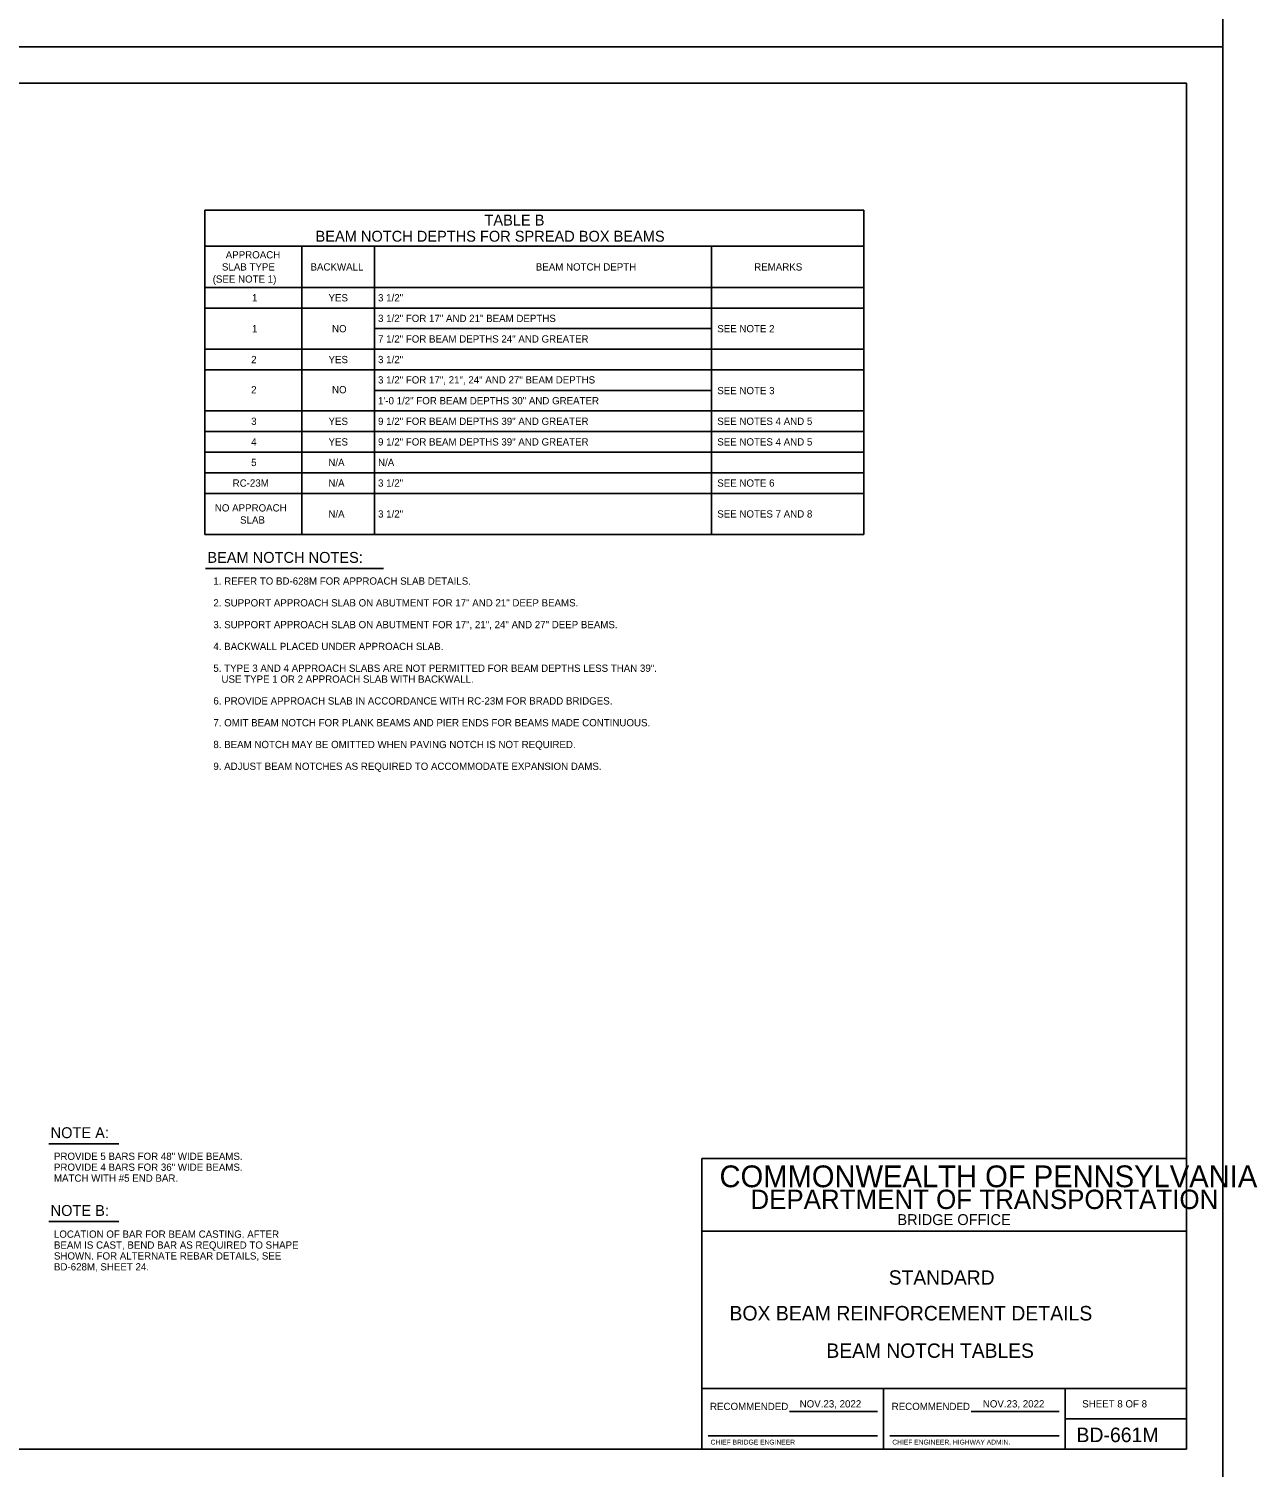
# Model space of a CAD drawing. Extents: x 639331 to 643089, y 299088 to 300975.
# Drawn here: x 642582 to 643089, y 299689 to 300283 of the extents above; entities that cross this region are included whole.
import ezdxf

# ---------------------------------------------------------------- set-up
doc = ezdxf.new("R2010")
doc.units = 0
for name, color, linetype in [('1', 7, 'Continuous'), ('DATES', 7, 'Continuous'), ('PLT-BNDY', 7, 'Continuous'), ('SIGNATORY TITLES', 7, 'Continuous')]:
    doc.layers.add(name, color=color, linetype=linetype)

msp = doc.modelspace()

# ---------------------------------------------------------------- linework, layer by layer
at = {"layer": '1'}
for p, q in [((643075.06, 300275.66), (643075.06, 300275.66)), ((642274.06, 300260.66), (643060.06, 300260.66)), ((643060.06, 300260.66), (643060.06, 299696.66)), ((642654.82, 300208.32), (642654.82, 300074.32)), ((642926.91, 300208.32), (642654.82, 300208.32)), ((642926.91, 300208.32), (642926.91, 300074.32)), ((642926.91, 300193.32), (642654.82, 300193.32)), ((642694.82, 300193.32), (642694.82, 300074.32)), ((642724.82, 300193.32), (642724.82, 300074.32)), ((642864.05, 300193.32), (642864.05, 300074.32)), ((642926.91, 300176.32), (642654.82, 300176.32)), ((642926.91, 300167.82), (642654.82, 300167.82)), ((642864.05, 300159.32), (642724.82, 300159.32)), ((642926.91, 300150.82), (642654.82, 300150.82)), ((642926.91, 300142.32), (642654.82, 300142.32)), ((642864.05, 300133.82), (642724.82, 300133.82)), ((642926.91, 300125.32), (642654.82, 300125.32)), ((642926.91, 300116.82), (642654.82, 300116.82)), ((642926.91, 300108.32), (642654.82, 300108.32)), ((642926.91, 300099.82), (642654.82, 300099.82)), ((642926.91, 300091.32), (642654.82, 300091.32)), ((642926.91, 300074.32), (642654.82, 300074.32)), ((642655.15, 300060.3), (642728.57, 300060.3)), ((642590.44, 299822.74), (642619.28, 299822.74)), ((643060.06, 299816.66), (642860.06, 299816.66)), ((642860.06, 299816.66), (642860.06, 299696.66)), ((643060.06, 299696.66), (643060.06, 299816.66)), ((642590.44, 299790.6), (642619.28, 299790.6)), ((643060.06, 299786.66), (642860.06, 299786.66)), ((643060.06, 299721.66), (642860.06, 299721.66)), ((642935.06, 299696.66), (642935.06, 299721.66)), ((643010.06, 299721.66), (643010.06, 299696.66)), ((642896.15, 299712.16), (642932.56, 299712.16)), ((642971.15, 299712.16), (643007.56, 299712.16)), ((643010.06, 299709.16), (643060.06, 299709.16)), ((642862.56, 299702.16), (642932.56, 299702.16)), ((642937.56, 299702.16), (643007.56, 299702.16)), ((643060.06, 299696.66), (642274.06, 299696.66)), ((642860.06, 299696.66), (643060.06, 299696.66))]:
    msp.add_line(p, q, dxfattribs=at)
at = {"layer": 'PLT-BNDY'}
for points in [[(642234.06, 300869.66), (643075.06, 300869.66), (643075.06, 300275.66), (642234.06, 300275.66)], [(642234.06, 300275.66), (643075.06, 300275.66), (643075.06, 299681.66), (642234.06, 299681.66)]]:
    msp.add_lwpolyline(points, close=True, dxfattribs=at)

# ---------------------------------------------------------------- texts
at = {"layer": '1'}
for s, height, p in [('TABLE B', 4.5, (642770.29, 300201.9)), ('BEAM NOTCH DEPTHS FOR SPREAD BOX BEAMS', 4.5, (642700.55, 300195.24)), ('3 1/2"', 3, (642726.35, 300170.57)), ('3 1/2" FOR 17" AND 21" BEAM DEPTHS', 3, (642726.35, 300162.07)), ('SEE NOTE 2', 3, (642866.39, 300157.82)), ('7 1/2" FOR BEAM DEPTHS 24" AND GREATER', 3, (642726.35, 300153.57)), ('3 1/2"', 3, (642726.35, 300145.07)), ('3 1/2" FOR 17", 21", 24" AND 27" BEAM DEPTHS', 3, (642726.35, 300136.68)), ('1\'-0 1/2" FOR BEAM DEPTHS 30" AND GREATER', 3, (642726.35, 300128.07)), ('SEE NOTE 3', 3, (642866.39, 300132.26)), ('9 1/2" FOR BEAM DEPTHS 39" AND GREATER', 3, (642726.35, 300119.57)), ('SEE NOTES 4 AND 5', 3, (642866.39, 300119.57)), ('9 1/2" FOR BEAM DEPTHS 39" AND GREATER', 3, (642726.35, 300111.07)), ('SEE NOTES 4 AND 5', 3, (642866.39, 300111.07)), ('N/A', 3, (642726.35, 300102.57)), ('3 1/2"', 3, (642726.35, 300094.07)), ('SEE NOTE 6', 3, (642866.39, 300094.07)), ('3 1/2"', 3, (642726.35, 300081.32)), ('SEE NOTES 7 AND 8', 3, (642866.39, 300081.32)), ('BEAM NOTCH NOTES:', 4.5, (642655.88, 300062.61)), (' 1. REFER TO BD-628M FOR APPROACH SLAB DETAILS.', 3, (642657.25, 300053.61)), (' 2. SUPPORT APPROACH SLAB ON ABUTMENT FOR 17" AND 21" DEEP BEAMS.', 3, (642657.25, 300044.61)), (' 3. SUPPORT APPROACH SLAB ON ABUTMENT FOR 17", 21", 24" AND 27" DEEP BEAMS.', 3, (642657.25, 300035.61)), (' 4. BACKWALL PLACED UNDER APPROACH SLAB.', 3, (642657.25, 300026.61)), (' 5. TYPE 3 AND 4 APPROACH SLABS ARE NOT PERMITTED FOR BEAM DEPTHS LESS THAN 39".', 3, (642657.25, 300017.61)), ('    USE TYPE 1 OR 2 APPROACH SLAB WITH BACKWALL.', 3, (642657.25, 300013.11)), (' 6. PROVIDE APPROACH SLAB IN ACCORDANCE WITH RC-23M FOR BRADD BRIDGES.', 3, (642657.25, 300004.11)), (' 7. OMIT BEAM NOTCH FOR PLANK BEAMS AND PIER ENDS FOR BEAMS MADE CONTINUOUS.', 3, (642657.25, 299995.11)), (' 8. BEAM NOTCH MAY BE OMITTED WHEN PAVING NOTCH IS NOT REQUIRED.', 3, (642657.25, 299986.11)), (' 9. ADJUST BEAM NOTCHES AS REQUIRED TO ACCOMMODATE EXPANSION DAMS.', 3, (642657.25, 299977.11)), ('NOTE A:', 4.5, (642591.17, 299825.05)), ('PROVIDE 5 BARS FOR 48" WIDE BEAMS.', 3, (642592.55, 299816.06)), ('PROVIDE 4 BARS FOR 36" WIDE BEAMS.', 3, (642592.55, 299811.56)), ('MATCH WITH #5 END BAR.', 3, (642592.55, 299807.06)), ('COMMONWEALTH OF PENNSYLVANIA', 9, (642867.31, 299804.78)), ('DEPARTMENT OF TRANSPORTATION', 8.0002, (642880.06, 299795.78)), ('NOTE B:', 4.5, (642591.17, 299792.92)), ('BRIDGE OFFICE', 4.5, (642940.74, 299789.16)), ('LOCATION OF BAR FOR BEAM CASTING. AFTER', 3, (642592.55, 299783.92)), ('BEAM IS CAST, BEND BAR AS REQUIRED TO SHAPE', 3, (642592.55, 299779.42)), ('SHOWN. FOR ALTERNATE REBAR DETAILS, SEE', 3, (642592.55, 299774.92)), ('BD-628M, SHEET 24.', 3, (642592.55, 299770.42)), ('STANDARD', 5.939, (642937.18, 299764.53)), ('BOX BEAM REINFORCEMENT DETAILS', 6, (642871.41, 299749.76)), ('BEAM NOTCH TABLES', 5.9393, (642911.46, 299734.33)), ('RECOMMENDED', 3, (642863.39, 299712.78)), ('RECOMMENDED', 3, (642938.39, 299712.78)), ('SHEET 8 OF 8', 3, (643017.05, 299713.84)), ('BD-661M', 6, (643014.68, 299699.53))]:
    msp.add_text(s, height=height, dxfattribs=at).set_placement(p)
for s, p in [('APPROACH', (642663.47, 300188.32)), ('SLAB TYPE', (642661.9, 300183.32)), ('BACKWALL', (642698.47, 300183.32)), ('BEAM NOTCH DEPTH', (642791.47, 300183.32)), ('REMARKS', (642881.63, 300183.32)), ('(SEE NOTE 1)', (642658.08, 300178.32)), ('1', (642674.31, 300170.57)), ('YES', (642705.9, 300170.57)), ('1', (642674.31, 300157.82)), ('NO', (642707.34, 300157.82)), ('2', (642673.97, 300145.07)), ('YES', (642705.9, 300145.07)), ('2', (642673.97, 300132.63)), ('NO', (642707.34, 300132.63)), ('3', (642673.97, 300119.57)), ('YES', (642705.9, 300119.57)), ('4', (642673.97, 300111.07)), ('YES', (642705.9, 300111.07)), ('5', (642673.97, 300102.57)), ('N/A', (642705.84, 300102.57)), ('RC-23M', (642666.32, 300094.07)), ('N/A', (642705.84, 300094.07)), ('NO APPROACH', (642658.97, 300083.82)), ('N/A', (642705.84, 300081.32)), ('SLAB', (642669.39, 300078.82))]:
    msp.add_text(s, height=3, rotation=360, dxfattribs=at).set_placement(p)
at = {"layer": 'DATES'}
for p in [(642900.4, 299713.84), (642976.01, 299713.84)]:
    msp.add_text('NOV.23, 2022', height=3, dxfattribs=at).set_placement(p)
at = {"layer": 'SIGNATORY TITLES'}
for s, p in [('CHIEF BRIDGE ENGINEER', (642863.65, 299698.53)), ('CHIEF ENGINEER, HIGHWAY ADMIN.', (642938.65, 299698.53))]:
    msp.add_text(s, height=2, dxfattribs=at).set_placement(p)

doc.saveas('drawing.dxf')
